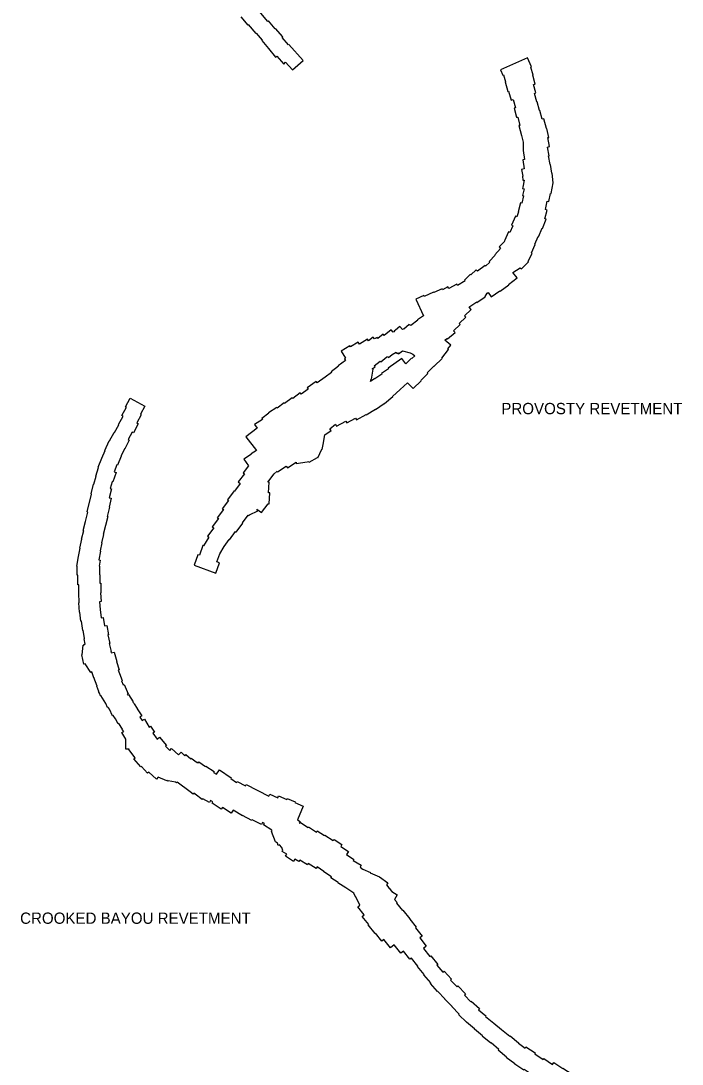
# Model space of a CAD drawing. Extents: x 2650582 to 3923188, y 277893 to 989177.
# Drawn here: x 3129613 to 3138986, y 835938 to 850733 of the extents above; entities that cross this region are included whole.
import ezdxf

# ---------------------------------------------------------------- set-up
doc = ezdxf.new("R2010")
doc.units = 0
doc.layers.add('Level 3', color=7, linetype='Continuous')

msp = doc.modelspace()

# ---------------------------------------------------------------- linework, layer by layer
at = {"layer": 'Level 3'}
for points in [[(3132733, 850788), (3132829, 850673), (3132835, 850679), (3132944, 850554), (3132948, 850557), (3133032, 850458), (3133028, 850455), (3133125, 850342), (3133122, 850340), (3133224, 850220), (3133239, 850233), (3133339, 850120), (3133365, 850145), (3133463, 850037), (3133612, 850173), (3133410, 850396), (3133406, 850393), (3133315, 850498), (3133324, 850506), (3133222, 850624), (3133219, 850621), (3133124, 850734), (3133115, 850726), (3132918, 850955)], [(3137128, 848283), (3137156, 848435), (3137143, 848571), (3137141, 848571), (3137120, 848697), (3137115, 848697), (3137094, 848817), (3137100, 848819), (3137077, 848944), (3137104, 848949), (3137082, 849077), (3137097, 849080), (3137069, 849208), (3137065, 849207), (3137028, 849344), (3137004, 849337), (3136969, 849462), (3136965, 849461), (3136931, 849585), (3136925, 849583), (3136892, 849704), (3136913, 849711), (3136879, 849831), (3136902, 849837), (3136868, 849961), (3136873, 849962), (3136840, 850077), (3136849, 850081), (3136793, 850208), (3136410, 850038), (3136444, 849961), (3136456, 849967), (3136484, 849868), (3136480, 849868), (3136517, 849733), (3136527, 849736), (3136563, 849610), (3136593, 849618), (3136625, 849500), (3136604, 849494), (3136640, 849365), (3136655, 849369), (3136688, 849251), (3136670, 849247), (3136708, 849107), (3136711, 849108), (3136732, 849012), (3136735, 849000), (3136731, 848894), (3136753, 848766), (3136726, 848761), (3136748, 848634), (3136710, 848627), (3136726, 848532), (3136722, 848532), (3136729, 848474), (3136745, 848475), (3136727, 848375), (3136723, 848356)], [(3136723, 848356), (3136746, 848351), (3136724, 848254), (3136738, 848251), (3136712, 848146), (3136696, 848150), (3136663, 848025), (3136668, 848024), (3136643, 847956), (3136622, 847964), (3136568, 847835), (3136585, 847827), (3136544, 847732), (3136526, 847741), (3136467, 847614), (3136474, 847611), (3136391, 847526), (3136411, 847506), (3136329, 847416), (3136336, 847409), (3136249, 847319), (3136259, 847309), (3136199, 847253), (3136192, 847262), (3136086, 847185), (3136067, 847204), (3135992, 847129), (3135983, 847138), (3135900, 847057), (3135910, 847046), (3135803, 846978), (3135792, 847000), (3135678, 846939), (3135665, 846961), (3135591, 846920), (3135585, 846933), (3135466, 846883), (3135464, 846886), (3135330, 846825), (3135324, 846838), (3135212, 846788), (3135318, 846552)], [(3136647, 847089), (3136587, 847165), (3136692, 847229), (3136708, 847215), (3136809, 847315), (3136806, 847318), (3136861, 847439), (3136849, 847445), (3136904, 847563), (3136899, 847565), (3136946, 847674), (3136950, 847672), (3137000, 847791), (3137008, 847788), (3137057, 847919), (3137039, 847926), (3137072, 848050), (3137048, 848057), (3137074, 848174), (3137095, 848169), (3137121, 848284), (3137128, 848283)], [(3135966, 846674), (3135977, 846677), (3135975, 846684), (3136074, 846746), (3136078, 846741), (3136194, 846821), (3136192, 846825), (3136222, 846869), (3136235, 846879), (3136277, 846817), (3136402, 846903), (3136405, 846899), (3136530, 846990), (3136526, 846995), (3136647, 847089)], [(3135318, 846552), (3135237, 846493), (3135241, 846488), (3135139, 846415), (3135132, 846423), (3135126, 846419), (3135119, 846427), (3135043, 846362), (3135041, 846366), (3135023, 846355), (3134985, 846399), (3134924, 846346), (3134911, 846335)], [(3135708, 846136), (3135624, 846203), (3135652, 846229), (3135658, 846222), (3135767, 846315), (3135746, 846339), (3135839, 846427), (3135825, 846442), (3135918, 846533), (3135903, 846548), (3135998, 846640), (3135966, 846674)], [(3134911, 846335), (3134898, 846324), (3134890, 846319), (3134863, 846353), (3134762, 846271), (3134746, 846291), (3134672, 846228)], [(3134073, 845014), (3134088, 844985), (3134219, 845054), (3134231, 845032), (3134358, 845099), (3134372, 845076), (3134505, 845151), (3134508, 845146), (3134638, 845225), (3134639, 845223), (3134764, 845308), (3134765, 845307), (3134886, 845404), (3134883, 845408), (3134988, 845507), (3134991, 845504), (3135091, 845602), (3135173, 845519), (3135285, 845628), (3135282, 845631), (3135381, 845730), (3135370, 845740), (3135466, 845837), (3135469, 845834), (3135583, 845946), (3135578, 845951), (3135675, 846074), (3135665, 846082), (3135708, 846136)], [(3134672, 846228), (3134662, 846244), (3134626, 846223), (3134606, 846247), (3134541, 846193), (3134525, 846219), (3134411, 846148), (3134394, 846176), (3134285, 846111), (3134277, 846124), (3134153, 846050), (3134213, 845950)], [(3134567, 845619), (3134579, 845652), (3134584, 845651), (3134605, 845793), (3134593, 845796), (3134634, 845825), (3134623, 845841), (3134708, 845906), (3134715, 845897), (3134798, 845967), (3134809, 845974), (3134814, 845966), (3134818, 845968), (3134825, 845960), (3134876, 846002), (3134932, 846035), (3134941, 846018), (3134955, 846026), (3134968, 846010), (3135023, 846054), (3135133, 846027), (3135169, 846008), (3135197, 845984)], [(3135197, 845984), (3135156, 845943), (3135148, 845948), (3135068, 845867), (3135014, 845944), (3134820, 845806), (3134825, 845799), (3134726, 845731), (3134731, 845724), (3134632, 845657), (3134628, 845662), (3134567, 845619)], [(3134213, 845950), (3134198, 845938), (3134213, 845918), (3134110, 845841), (3134115, 845835), (3134009, 845755), (3134016, 845744), (3133926, 845678), (3133924, 845681), (3133812, 845598), (3133797, 845619), (3133673, 845528), (3133686, 845509), (3133588, 845437), (3133571, 845458), (3133466, 845379), (3133459, 845388), (3133352, 845308), (3133346, 845316), (3133246, 845242), (3133239, 845252), (3133125, 845175), (3133129, 845168), (3133028, 845096), (3133037, 845082), (3132926, 845007), (3132960, 844957)], [(3130554, 843768), (3130616, 844022), (3130607, 844025), (3130642, 844163), (3130648, 844161), (3130682, 844274), (3130673, 844278), (3130715, 844400), (3130709, 844402), (3130760, 844531), (3130762, 844531), (3130807, 844638), (3130801, 844641), (3130866, 844777), (3130871, 844775), (3130935, 844897), (3130941, 844894), (3131003, 845005), (3130997, 845008), (3131062, 845126), (3131043, 845136), (3131108, 845254), (3131095, 845261), (3131160, 845382), (3131372, 845269), (3131310, 845153), (3131320, 845148), (3131256, 845031), (3131277, 845019), (3131208, 844892), (3131192, 844901), (3131132, 844794), (3131148, 844786), (3131084, 844663), (3131080, 844665), (3131032, 844564), (3131035, 844562), (3130982, 844433), (3130975, 844436), (3130936, 844336), (3130964, 844327), (3130918, 844194), (3130908, 844197), (3130879, 844103), (3130897, 844098), (3130865, 843970), (3130892, 843962), (3130862, 843837), (3130869, 843835)], [(3132960, 844957), (3132802, 844832), (3132953, 844640), (3132876, 844593), (3132880, 844587), (3132774, 844518), (3132837, 844421)], [(3133923, 844863), (3134012, 844922), (3133994, 844947), (3134073, 845014)], [(3133670, 844481), (3133693, 844482), (3133699, 844473), (3133816, 844541), (3133823, 844538), (3133877, 844657), (3133883, 844656), (3133896, 844723), (3133923, 844863)], [(3132759, 843608), (3132753, 843612), (3132835, 843721), (3132841, 843716), (3132852, 843730), (3132971, 843783), (3132959, 843810), (3133025, 843761), (3133119, 843886), (3133132, 843885), (3133140, 844040), (3133125, 844041), (3133134, 844191), (3133114, 844192), (3133201, 844310), (3133245, 844347), (3133250, 844339), (3133372, 844420), (3133390, 844393), (3133513, 844475), (3133515, 844458), (3133671, 844478), (3133670, 844481)], [(3132837, 844421), (3132763, 844324), (3132781, 844310), (3132694, 844194), (3132722, 844173), (3132640, 844064), (3132636, 844066), (3132542, 843941), (3132554, 843932), (3132467, 843815)], [(3130525, 841896), (3130509, 841970), (3130516, 841972), (3130496, 842090), (3130491, 842089), (3130470, 842218), (3130463, 842218), (3130449, 842347), (3130443, 842347), (3130435, 842480), (3130440, 842480), (3130432, 842622), (3130434, 842622), (3130432, 842737), (3130422, 842737), (3130421, 842871), (3130409, 842871), (3130412, 842998), (3130406, 842999), (3130428, 843136), (3130431, 843136), (3130454, 843254), (3130448, 843255), (3130476, 843382), (3130473, 843382), (3130506, 843506), (3130497, 843508), (3130530, 843634), (3130527, 843635), (3130561, 843767), (3130554, 843768)], [(3130869, 843835), (3130837, 843705), (3130844, 843703), (3130779, 843449), (3130786, 843447), (3130756, 843332), (3130762, 843331), (3130736, 843215), (3130741, 843214), (3130716, 843090), (3130736, 843087), (3130722, 843000), (3130729, 843000), (3130726, 842879), (3130730, 842879), (3130731, 842761), (3130746, 842761), (3130748, 842624), (3130743, 842624), (3130750, 842498), (3130728, 842496), (3130735, 842384), (3130737, 842384), (3130750, 842266), (3130781, 842271), (3130800, 842153), (3130830, 842158), (3130853, 842025), (3130846, 842024), (3130872, 841905), (3130864, 841903), (3130893, 841790), (3130886, 841788), (3130892, 841769)], [(3132467, 843815), (3132483, 843803), (3132395, 843687), (3132413, 843674), (3132326, 843557), (3132346, 843542), (3132258, 843425), (3132275, 843412), (3132203, 843287), (3132193, 843291), (3132143, 843154), (3132122, 843161), (3132069, 843015), (3132377, 842902), (3132430, 843048), (3132392, 843062), (3132433, 843174), (3132494, 843280), (3132565, 843376), (3132569, 843373), (3132657, 843490), (3132666, 843483), (3132759, 843608)], [(3130619, 841503), (3130605, 841494), (3130524, 841614), (3130507, 841610), (3130478, 841741), (3130482, 841742), (3130498, 841879), (3130509, 841878), (3130506, 841891), (3130525, 841896)], [(3130892, 841769), (3130936, 841782), (3130975, 841649), (3130969, 841648), (3131006, 841532), (3130992, 841527), (3131010, 841477), (3131012, 841478), (3131048, 841378), (3131041, 841376), (3131064, 841317), (3131077, 841322), (3131135, 841191), (3131120, 841184)], [(3130748, 841164), (3130742, 841162), (3130727, 841200), (3130714, 841221), (3130718, 841223), (3130688, 841298), (3130692, 841299), (3130649, 841419), (3130647, 841418), (3130619, 841503)], [(3131000, 840770), (3130990, 840764), (3130952, 840836), (3130922, 840884), (3130913, 840879), (3130867, 840970), (3130853, 840992), (3130851, 840990), (3130846, 840999), (3130841, 840996), (3130816, 841050), (3130748, 841164)], [(3131120, 841184), (3131126, 841174), (3131139, 841182), (3131205, 841076), (3131201, 841073), (3131213, 841055), (3131214, 841056), (3131218, 841048), (3131262, 840981), (3131259, 840979), (3131328, 840878), (3131298, 840858), (3131334, 840812), (3131365, 840831)], [(3131365, 840831), (3131433, 840717), (3131452, 840729), (3131507, 840647), (3131483, 840630), (3131545, 840547), (3131576, 840574), (3131675, 840457), (3131665, 840449), (3131725, 840387), (3131750, 840413), (3131846, 840324), (3131883, 840361), (3131935, 840309), (3131952, 840328), (3132020, 840267)], [(3131828, 839936), (3131818, 839926), (3131805, 839939), (3131702, 839958), (3131694, 839951), (3131682, 839963), (3131680, 839957), (3131559, 840006), (3131534, 839979), (3131426, 840078), (3131409, 840064), (3131323, 840160), (3131313, 840152), (3131215, 840268), (3131231, 840283), (3131143, 840400), (3131149, 840405), (3131102, 840404), (3131100, 840545), (3131044, 840639), (3131070, 840655), (3131048, 840682), (3131055, 840687), (3131000, 840770)], [(3132020, 840267), (3132027, 840277), (3132110, 840216), (3132125, 840211), (3132133, 840223), (3132231, 840159), (3132233, 840163), (3132353, 840088), (3132344, 840074), (3132388, 840052), (3132426, 840110), (3132595, 839998), (3132589, 839988), (3132670, 839930), (3132674, 839935), (3132681, 839948), (3132798, 839886), (3132808, 839902), (3133127, 839739), (3133141, 839768), (3133253, 839716), (3133266, 839745), (3133382, 839692), (3133388, 839706), (3133502, 839656), (3133498, 839648), (3133616, 839596), (3133536, 839403)], [(3133024, 839335), (3132892, 839402), (3132885, 839391), (3132755, 839463), (3132754, 839461), (3132624, 839542), (3132594, 839496), (3132470, 839577), (3132453, 839552), (3132323, 839639), (3132335, 839656), (3132299, 839675), (3132285, 839650), (3132190, 839701), (3132182, 839691), (3132084, 839767), (3132063, 839780), (3132053, 839768), (3132012, 839801), (3132012, 839801), (3131828, 839936)], [(3134333, 838362), (3134218, 838436), (3134219, 838438), (3134108, 838508), (3134111, 838513), (3134006, 838581), (3134015, 838596), (3133906, 838667), (3133909, 838672), (3133812, 838735), (3133797, 838712), (3133687, 838784), (3133675, 838764), (3133565, 838833), (3133553, 838814), (3133498, 838847), (3133477, 838814), (3133363, 838887), (3133381, 838916), (3133318, 838955), (3133325, 838966), (3133310, 839008), (3133278, 839046), (3133261, 839041), (3133252, 839073), (3133224, 839091), (3133165, 839239), (3133177, 839244), (3133164, 839252), (3133168, 839257), (3133053, 839332), (3133064, 839350), (3133038, 839363), (3133024, 839335)], [(3133536, 839403), (3133572, 839380), (3133559, 839359), (3133567, 839354), (3133575, 839366), (3133687, 839295), (3133691, 839301), (3133804, 839229), (3133814, 839245), (3133917, 839181), (3133920, 839186), (3134040, 839108), (3134052, 839125), (3134164, 839051), (3134147, 839025), (3134256, 838955), (3134228, 838909), (3134333, 838842), (3134325, 838828), (3134436, 838758), (3134420, 838732)], [(3134420, 838732), (3134438, 838724), (3134436, 838719), (3134462, 838702), (3134567, 838656), (3134565, 838651), (3134696, 838594), (3134695, 838592), (3134816, 838511), (3134795, 838481), (3134830, 838438), (3134848, 838426), (3134845, 838420), (3134872, 838386), (3134948, 838337), (3134908, 838274), (3134945, 838228), (3134937, 838222), (3135023, 838116), (3135028, 838120), (3135127, 837999), (3135124, 837996), (3135218, 837880), (3135207, 837871), (3135301, 837755), (3135267, 837727), (3135360, 837609)], [(3135128, 837426), (3135035, 837542), (3134997, 837512), (3134902, 837629), (3134853, 837588), (3134760, 837705), (3134730, 837680), (3134638, 837794), (3134635, 837792), (3134537, 837913), (3134544, 837919), (3134453, 838032), (3134480, 838055), (3134390, 838168), (3134419, 838192), (3134362, 838312), (3134357, 838310), (3134333, 838362)], [(3135360, 837609), (3135320, 837576), (3135410, 837464), (3135423, 837474), (3135521, 837352), (3135507, 837341), (3135594, 837243), (3135611, 837258), (3135715, 837141), (3135704, 837131), (3135797, 837036), (3135808, 837047), (3135917, 836936), (3135899, 836918), (3135991, 836824), (3135998, 836831), (3136113, 836726), (3136098, 836710), (3136205, 836622), (3136200, 836616), (3136316, 836520), (3136315, 836519), (3136426, 836428), (3136428, 836431), (3136545, 836334)], [(3136390, 836146), (3136278, 836239), (3136275, 836235), (3136154, 836334), (3136158, 836339), (3136042, 836434), (3136045, 836438), (3135930, 836534), (3135931, 836535), (3135819, 836636), (3135828, 836647), (3135723, 836754), (3135726, 836757), (3135620, 836864), (3135623, 836866), (3135521, 836969), (3135520, 836968), (3135417, 837084), (3135424, 837091), (3135324, 837203), (3135328, 837207), (3135235, 837323), (3135240, 837328), (3135148, 837441), (3135128, 837426)], [(3136545, 836334), (3136549, 836338), (3136669, 836240), (3136666, 836236), (3136763, 836165), (3136773, 836182), (3136904, 836097), (3136897, 836085), (3137017, 836006), (3137024, 836017), (3137150, 835935), (3137166, 835960), (3137293, 835878), (3137296, 835883), (3137427, 835798), (3137534, 835728)], [(3137402, 835501), (3137282, 835579), (3137281, 835578), (3137155, 835660), (3137148, 835650), (3137023, 835732), (3137010, 835712), (3136884, 835794), (3136873, 835778), (3136748, 835860), (3136743, 835853), (3136613, 835939), (3136615, 835941), (3136493, 836031), (3136498, 836038), (3136380, 836134), (3136390, 836146)]]:
    msp.add_lwpolyline(points, dxfattribs=at)

# ---------------------------------------------------------------- texts
for s, p in [('PROVOSTY REVETMENT', (3136423, 845155)), ('CROOKED BAYOU REVETMENT', (3129602, 837928))]:
    msp.add_text(s, height=160, dxfattribs=at).set_placement(p)

doc.saveas('drawing.dxf')
